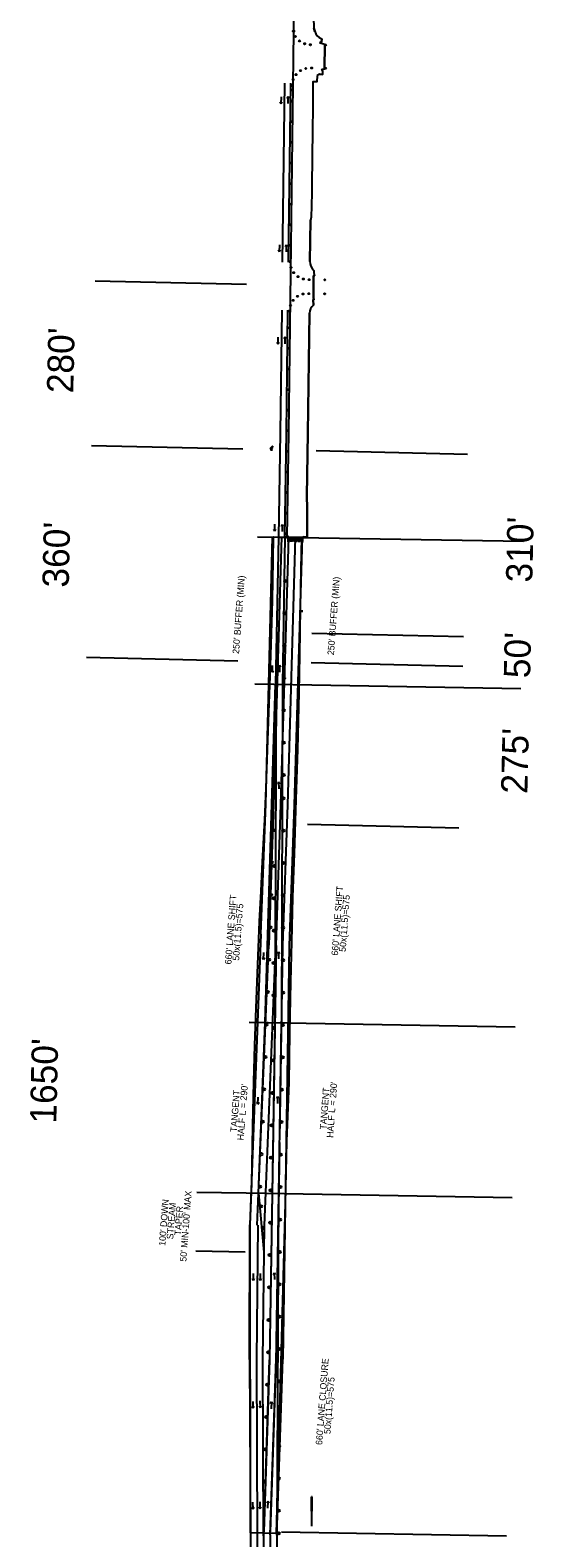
# Model space of a CAD drawing. Extents: x 1650647 to 1653016, y 602856 to 611467.
# Drawn here: x 1652100 to 1652957, y 604352 to 606913 of the extents above; entities that cross this region are included whole.
import ezdxf

# ---------------------------------------------------------------- set-up
doc = ezdxf.new("R2010")
doc.units = 0
for name, color, linetype in [('CM_Corridor_Design', 7, 'Continuous'), ('Default', 7, 'Continuous'), ('DT_X_Break_Line', 7, 'Continuous'), ('DT_X_Contour_Major', 7, 'Continuous'), ('DT_X_Void', 7, 'Continuous'), ('GE_P_Alignment_500_Bearings', 7, 'Continuous'), ('GE_P_Alignment_500_Stations', 7, 'Continuous'), ('MD_P_Intersection_MatchLine', 7, 'Continuous'), ('PF_P_Grade_Line', 7, 'Continuous'), ('PF_X_Ground_Line', 7, 'Continuous'), ('PF_X_Ground_Line_RT', 7, 'Continuous'), ('PV_P_Curb', 7, 'Continuous'), ('PV_P_EOP', 7, 'Continuous'), ('PV_X_EOP', 7, 'Continuous'), ('SC_Scratch1', 7, 'Continuous'), ('UT_X_Water', 7, 'Continuous')]:
    doc.layers.add(name, color=color, linetype=linetype)

msp = doc.modelspace()

# ---------------------------------------------------------------- linework, layer by layer
at = {"layer": 'CM_Corridor_Design'}
for p, q in [((1652527.1, 606787.9), (1652525.5, 606791.3)), ((1652527.1, 606787.9), (1652527.3, 606799.8)), ((1652527.1, 606787.9), (1652528.9, 606791.3)), ((1652538.4, 606800.7), (1652536.6, 606797.4)), ((1652538.4, 606800.7), (1652538.3, 606788.9)), ((1652538.4, 606800.7), (1652540.1, 606797.3)), ((1652524.3, 606536.8), (1652522.6, 606540.2)), ((1652524.3, 606536.8), (1652524.5, 606548.7)), ((1652524.3, 606536.8), (1652526.1, 606540.2)), ((1652535.6, 606548.8), (1652533.8, 606545.4)), ((1652535.6, 606548.8), (1652535.4, 606536.9)), ((1652535.6, 606548.8), (1652537.2, 606545.4)), ((1652521.7, 606380), (1652520, 606383.4)), ((1652521.7, 606380), (1652521.8, 606391.9)), ((1652521.7, 606380), (1652523.5, 606383.4)), ((1652533.4, 606392.3), (1652531.6, 606388.9)), ((1652533.4, 606392.3), (1652533.3, 606380.4)), ((1652533.4, 606392.3), (1652535.1, 606388.9)), ((1652516.3, 606062.2), (1652514.7, 606065.6)), ((1652516.3, 606062.2), (1652516.5, 606074.1)), ((1652516.3, 606062.2), (1652518.1, 606065.6)), ((1652528.7, 606073.6), (1652526.9, 606070.2)), ((1652528.7, 606073.6), (1652528.6, 606061.7)), ((1652528.7, 606073.6), (1652530.4, 606070.2)), ((1652512.3, 605822.3), (1652512.4, 605834.1)), ((1652524.3, 605834.6), (1652522.6, 605831.2)), ((1652524.3, 605834.6), (1652524.2, 605822.7)), ((1652524.3, 605834.6), (1652526, 605831.2)), ((1652512.3, 605822.3), (1652510.6, 605825.7)), ((1652512.3, 605822.3), (1652514.1, 605825.6)), ((1652522.7, 605636.4), (1652521.1, 605633)), ((1652522.7, 605636.4), (1652522.9, 605624.5)), ((1652522.7, 605636.4), (1652524.5, 605633)), ((1652497.1, 605334.3), (1652497.6, 605346.1)), ((1652522.4, 605347.5), (1652520.7, 605344.2)), ((1652522.4, 605347.5), (1652522.6, 605335.7)), ((1652522.4, 605347.5), (1652524.2, 605344.2)), ((1652497.1, 605334.3), (1652495.5, 605337.7)), ((1652497.1, 605334.3), (1652499, 605337.6)), ((1652487.6, 605088.7), (1652486.1, 605092.1)), ((1652487.6, 605088.7), (1652488.1, 605100.5)), ((1652487.6, 605088.7), (1652489.5, 605092)), ((1652520.6, 605101.6), (1652518.9, 605098.2)), ((1652520.6, 605101.6), (1652520.7, 605089.8)), ((1652520.6, 605101.6), (1652522.3, 605098.3)), ((1652479.7, 604788.9), (1652478.1, 604792.3)), ((1652479.7, 604788.9), (1652479.9, 604800.8)), ((1652479.7, 604788.9), (1652481.5, 604792.3)), ((1652491.8, 604789.2), (1652490.2, 604792.6)), ((1652491.8, 604789.2), (1652492, 604801)), ((1652491.8, 604789.2), (1652493.6, 604792.5)), ((1652515.3, 604802.2), (1652513.6, 604798.8)), ((1652515.3, 604802.2), (1652515.4, 604790.4)), ((1652515.3, 604802.2), (1652517, 604798.9)), ((1652479.6, 604571.8), (1652479.4, 604583.6)), ((1652491.7, 604572.5), (1652491.5, 604584.3)), ((1652510.4, 604582.7), (1652508.5, 604579.4)), ((1652510.4, 604582.7), (1652509.9, 604570.8)), ((1652510.4, 604582.7), (1652512, 604579.2)), ((1652479.6, 604571.8), (1652477.8, 604575.1)), ((1652479.6, 604571.8), (1652481.3, 604575.2)), ((1652491.7, 604572.5), (1652489.9, 604575.8)), ((1652491.7, 604572.5), (1652493.4, 604575.9)), ((1652479.3, 604400.6), (1652477.5, 604403.9)), ((1652479.3, 604400.6), (1652479, 604412.4)), ((1652479.3, 604400.6), (1652480.9, 604404)), ((1652491.4, 604401.3), (1652489.6, 604404.6)), ((1652491.4, 604401.3), (1652491.1, 604413.1)), ((1652491.4, 604401.3), (1652493, 604404.7)), ((1652504.2, 604413.8), (1652502.4, 604410.5)), ((1652504.2, 604413.8), (1652503.8, 604402)), ((1652504.2, 604413.8), (1652505.8, 604410.4))]:
    msp.add_line(p, q, dxfattribs=at)
at = {"layer": 'Default'}
msp.add_lwpolyline([(1652561.5, 606051.4), (1652560.7, 605997.6), (1652559.5, 605931.6), (1652558.1, 605851.7), (1652556.8, 605787.9), (1652554.7, 605691), (1652552.1, 605605.9), (1652548.9, 605514.1), (1652546.4, 605440.2), (1652544.3, 605364.6), (1652542.7, 605296.2), (1652541.1, 605209.6), (1652539.8, 605125.1), (1652536.1, 605025.9), (1652533.9, 604920.6), (1652518.7, 604359.2), (1652474.9, 604360), (1652474.2, 604883.4), (1652477.4, 604953.6), (1652478.9, 605051.2), (1652480.7, 605126.3), (1652482.5, 605188.7), (1652484.6, 605251.8), (1652486.1, 605296.5), (1652488.3, 605354.7), (1652490, 605399), (1652492.8, 605450.4), (1652495.3, 605500.8), (1652499, 605571.5), (1652501.4, 605625.4), (1652503.9, 605690.8), (1652506.2, 605754), (1652508.3, 605815.7), (1652510.1, 605869.3), (1652512, 605944.5), (1652513.5, 606013), (1652513.9, 606052.2)], close=True, dxfattribs=at)
at = {"layer": 'DT_X_Break_Line'}
for centre, radius in [((1652547.7, 606911.6), 1), ((1652551.5, 606902.4), 1), ((1652558.2, 606895), 1), ((1652566.9, 606890.2), 1), ((1652576.7, 606888.5), 1), ((1652602.4, 606888.1), 1), ((1652552.3, 606837.8), 1), ((1652559.8, 606844.4), 1), ((1652569, 606848.2), 1), ((1652578.9, 606848.9), 1), ((1652602.5, 606848.4), 1), ((1652545.6, 606811.7), 1), ((1652545.7, 606819.3), 1), ((1652547.4, 606829.1), 1), ((1652545.4, 606792.6), 1), ((1652545, 606757.6), 1), ((1652544.6, 606722.6), 1), ((1652544.1, 606687.6), 1), ((1652543.7, 606652.6), 1), ((1652543.3, 606617.6), 1), ((1652542.9, 606582.6), 1), ((1652542.4, 606547.6), 1), ((1652542, 606519.9), 1), ((1652543.6, 606510.1), 1), ((1652548.2, 606501.3), 1), ((1652555.5, 606494.5), 1), ((1652564.6, 606490.5), 1), ((1652574.5, 606489.5), 1), ((1652601.3, 606489.2), 1), ((1652542.8, 606445.9), 1), ((1652547.5, 606454.3), 1), ((1652554.8, 606461), 1), ((1652564, 606464.9), 1), ((1652573.9, 606465.7), 1), ((1652601, 606465.4), 1), ((1652541, 606436.1), 1), ((1652540.8, 606407.6), 1), ((1652540.3, 606372.6), 1), ((1652539.9, 606337.6), 1), ((1652539.5, 606302.6), 1), ((1652539.1, 606267.6), 1), ((1652538.6, 606232.7), 1), ((1652538.1, 606197.7), 1), ((1652537.5, 606162.7), 1), ((1652536.9, 606127.7), 1), ((1652536.3, 606092.7), 1), ((1652535.5, 606051.8), 1), ((1652535.6, 606057.7), 1), ((1652534, 605977.5), 2), ((1652533, 605922.6), 2), ((1652532.5, 605867.6), 2), ((1652531.6, 605812.7), 2), ((1652531.3, 605757.8), 2), ((1652531.1, 605702.9), 2), ((1652531, 605647.9), 2), ((1652514.6, 605608.7), 2), ((1652530.8, 605608.1), 2), ((1652513.4, 605553.6), 2), ((1652530.7, 605553.2), 2), ((1652510.6, 605499.2), 2), ((1652530.4, 605498.3), 2), ((1652515.1, 605493.4), 2), ((1652509.8, 605443.7), 2), ((1652514.7, 605438.3), 2), ((1652530.2, 605443.2), 2), ((1652508.4, 605388.9), 2), ((1652514.6, 605383.3), 2), ((1652530.2, 605388.2), 2), ((1652506.3, 605333.8), 2), ((1652514.3, 605328.2), 2), ((1652530, 605333.2), 2), ((1652504.2, 605278.9), 2), ((1652514.2, 605273.2), 2), ((1652529.9, 605278.1), 2), ((1652501.9, 605223.8), 2), ((1652514, 605217.7), 2), ((1652529.6, 605223.2), 2), ((1652499.8, 605168.9), 2), ((1652529.3, 605168.2), 2), ((1652513.2, 605162.8), 2), ((1652497.6, 605113.8), 2), ((1652528.1, 605113.1), 2), ((1652512.1, 605107.6), 2), ((1652495.5, 605058.7), 2), ((1652511, 605052.5), 2), ((1652527, 605058), 2), ((1652493.1, 605003.6), 2), ((1652509.9, 604997.4), 2), ((1652526.3, 605002.8), 2), ((1652490.8, 604948.4), 2), ((1652509.3, 604942.2), 2), ((1652525.5, 604947.7), 2), ((1652492.7, 604915.1), 2), ((1652508.3, 604887.3), 2), ((1652524.8, 604892.5), 2), ((1652495.9, 604878.4), 2), ((1652507.6, 604832.1), 2), ((1652524.6, 604837.6), 2), ((1652524.1, 604782.7), 2), ((1652506.8, 604777.2), 2), ((1652505.8, 604722.1), 2), ((1652524, 604727.5), 2), ((1652504.9, 604667.1), 2), ((1652523.7, 604672.6), 2), ((1652503.4, 604612.1), 2), ((1652503.4, 604612.1), 2), ((1652523.5, 604617.7), 2), ((1652523.5, 604617.7), 2), ((1652501.7, 604557.3), 2), ((1652523.3, 604562.8), 2), ((1652499.9, 604502.1), 2), ((1652523.1, 604507.8), 2), ((1652498.3, 604447.2), 2), ((1652522.9, 604452.9), 2), ((1652522.7, 604398), 2), ((1652522.9, 604359.6), 2)]:
    msp.add_circle(centre, radius, dxfattribs=at)
at = {"layer": 'DT_X_Contour_Major'}
for p, q in [((1652548.3, 606910.6), (1652548.3, 606912.4)), ((1652584.1, 606911.2), (1652582.6, 606916.8)), ((1652595.4, 606892.9), (1652592.3, 606891.9)), ((1652595.4, 606892.9), (1652595.9, 606898.5)), ((1652600.4, 606846.9), (1652601.1, 606889.7)), ((1652592.4, 606838.4), (1652597.2, 606838.2)), ((1652600.4, 606846.9), (1652596.3, 606846.4)), ((1652597.2, 606844.4), (1652596.3, 606846.4)), ((1652597.2, 606844.4), (1652597.2, 606838.2)), ((1652580.8, 606807.8), (1652580.6, 606794)), ((1652576, 606520.2), (1652576.9, 606590.3)), ((1652581.7, 606457.6), (1652582.2, 606496)), ((1652582.2, 606496), (1652583.4, 606496.7)), ((1652537, 606051.8), (1652564.5, 606051.3)), ((1652564.5, 606051.3), (1652564.6, 606052.2)), ((1652571.1, 606052.1), (1652564.6, 606052.2))]:
    msp.add_line(p, q, dxfattribs=at)
for points in [[(1652548.3, 606912.4), (1652551.8, 607199.3), (1652552.1, 607225.4)], [(1652584.6, 607225.2), (1652582, 607012), (1652582, 607012), (1652582, 607012), (1652582, 607012), (1652581.7, 606935.1), (1652582.6, 606916.7), (1652582.6, 606916.8), (1652582.6, 606916.6), (1652582.6, 606916.7), (1652584, 606911.4)], [(1652537.5, 606051.8), (1652537, 606051.8), (1652540, 606229.1), (1652548.3, 606910.8)], [(1652595.9, 606898.5), (1652595.4, 606892.9), (1652592.3, 606891.9)], [(1652601.1, 606889.7), (1652600.4, 606846.9), (1652596.3, 606846.4), (1652597.2, 606844.4), (1652597.2, 606838.2), (1652592.4, 606838.4)], [(1652588.2, 606836.1), (1652587.9, 606825.7), (1652580.9, 606825.6), (1652580.8, 606807.8), (1652580.6, 606794), (1652580.2, 606731.2), (1652579.9, 606709.3), (1652578.9, 606637.3), (1652578.6, 606614.6), (1652578, 606595.3), (1652576.9, 606590.2), (1652576.9, 606590.3), (1652576.9, 606590.1), (1652576.9, 606590.2), (1652576, 606520.9)], [(1652588.2, 606836.1), (1652587.9, 606825.7), (1652580.9, 606825.6), (1652580.8, 606807.8)], [(1652580.6, 606794), (1652580.2, 606731.2), (1652579.9, 606709.3), (1652578.9, 606637.3), (1652578.6, 606614.6), (1652578, 606595.3), (1652576.9, 606590.1)], [(1652582.5, 606505.1), (1652582.3, 606501.1), (1652583.4, 606496.7), (1652582.2, 606496), (1652581.7, 606457.6), (1652582.9, 606456), (1652581.4, 606454.9), (1652581.7, 606445.8)], [(1652582.5, 606505.1), (1652582.3, 606501.1), (1652583.4, 606496.7)], [(1652581.7, 606445.8), (1652581.4, 606454.9), (1652582.9, 606456), (1652581.7, 606457.6)], [(1652575, 606432.5), (1652572.5, 606228.6), (1652570.7, 606121.8), (1652570.7, 606121.8), (1652570.7, 606121.8), (1652570.7, 606121.8), (1652571.1, 606101.9), (1652571.3, 606077.5), (1652571.1, 606052.1), (1652564.6, 606052.2), (1652564.5, 606051.3), (1652539.5, 606051.7)], [(1652570.7, 606121.8), (1652572.5, 606228.6), (1652575, 606432.5)], [(1652571.1, 606052.1), (1652571.3, 606077.5), (1652571.1, 606101.9), (1652570.7, 606121.8)]]:
    msp.add_lwpolyline(points, dxfattribs=at)
for centre, radius, start, end in [((1652548.8, 606911.6), 1, 236.0828, 122.529), ((1652602.4, 606916.4), 19, 195.042, 250.167), ((1652602.4, 606916.4), 19, 195.042, 250.167), ((1652603.1, 606916.6), 27, 246.3312, 265.7395), ((1652603.1, 606916.6), 27, 246.3312, 265.7395), ((1652600.2, 606819.5), 20.5, 112.4368, 125.8239), ((1652600.2, 606819.5), 20.5, 112.4368, 125.8239), ((1652598, 606520.6), 22, 179.3069, 225.0406), ((1652598, 606520.6), 22, 179.3069, 225.0406), ((1652592, 606432.3), 17, 127.2779, 179.3069), ((1652592, 606432.3), 17, 127.2779, 179.3069), ((1652538.5, 606051.8), 1, 359.0173, 179.0173)]:
    msp.add_arc(centre, radius, start, end, dxfattribs=at)
at = {"layer": 'DT_X_Void'}
for p, q in [((1652539.5, 606048.4), (1652549.5, 606048.3)), ((1652539.5, 606046.4), (1652549.5, 606046.3)), ((1652546.5, 606044.9), (1652542.5, 606044.9)), ((1652543.5, 606046.4), (1652543.5, 606044.9)), ((1652544.5, 606047.4), (1652544.5, 606047.4)), ((1652545.5, 606046.4), (1652545.5, 606044.9)), ((1652552.4, 606048.4), (1652562.4, 606048.3)), ((1652552.4, 606046.4), (1652562.4, 606046.3)), ((1652559.4, 606044.8), (1652555.4, 606044.8)), ((1652556.4, 606046.3), (1652556.4, 606044.8)), ((1652557.4, 606047.3), (1652557.4, 606047.3)), ((1652558.4, 606046.3), (1652558.4, 606044.8))]:
    msp.add_line(p, q, dxfattribs=at)
for points in [[(1652538.6, 606050.5), (1652538.5, 606044.5), (1652539.5, 606044.4), (1652539.6, 606050.4)], [(1652550.6, 606050.3), (1652550.5, 606044.3), (1652549.5, 606044.3), (1652549.6, 606050.3)], [(1652551.4, 606050.4), (1652551.4, 606044.4), (1652552.4, 606044.4), (1652552.4, 606050.4)], [(1652563.4, 606050.3), (1652563.4, 606044.3), (1652562.4, 606044.3), (1652562.4, 606050.3)]]:
    msp.add_lwpolyline(points, close=True, dxfattribs=at)
at = {"layer": 'GE_P_Alignment_500_Bearings'}
for p, q in [((1652500, 605227.3), (1652517.6, 605802.1)), ((1652518.6, 605802.1), (1652516.3, 605226.9)), ((1652488.2, 604937.5), (1652500, 605227.3)), ((1652516.3, 605227), (1652511.5, 604937.1)), ((1652488.2, 604937.5), (1652497.4, 604837.3))]:
    msp.add_line(p, q, dxfattribs=at)
msp.add_lwpolyline([(1652511.5, 604937.1), (1652507, 604654.3), (1652497.6, 604362.2)], dxfattribs=at)
at = {"layer": 'GE_P_Alignment_500_Stations'}
msp.add_lwpolyline([(1652508.6, 604362), (1652518.3, 604648.3), (1652522.8, 604936.9)], dxfattribs=at)
at = {"layer": 'MD_P_Intersection_MatchLine'}
for p, q in [((1652510.8, 606204.9), (1652512, 606204.9)), ((1652511.2, 606206.1), (1652512, 606206.1))]:
    msp.add_line(p, q, dxfattribs=at)
msp.add_lwpolyline([(1652511.2, 606206.1), (1652509.6, 606200.1), (1652512, 606200.1)], dxfattribs=at)
msp.add_circle((1652510.3, 606202.9), 1.3, dxfattribs=at)
msp.add_arc((1652512, 606205.5), 0.638, 268.8767, 91.1233, dxfattribs=at)
at = {"layer": 'PF_P_Grade_Line'}
for p, q in [((1652527.5, 606052.2), (1652514, 605598)), ((1652551, 606051.5), (1652537.5, 605597.3)), ((1652514, 605598.1), (1652505.8, 605358.8)), ((1652537.5, 605597.3), (1652529.3, 605358.1)), ((1652505.3, 605358.9), (1652485.9, 604882.9)), ((1652529.3, 605358.1), (1652524.2, 605028.7)), ((1652524.2, 605023.7), (1652518.5, 604655.6)), ((1652487.4, 604882.7), (1652484.9, 604654.5)), ((1652484.9, 604654.5), (1652486.4, 604355.4)), ((1652508.4, 604356.6), (1652518.5, 604655.6)), ((1652486.4, 604355.4), (1652478.6, 603642.8)), ((1652508.4, 604356.6), (1652500.6, 603644))]:
    msp.add_line(p, q, dxfattribs=at)
at = {"layer": 'PF_X_Ground_Line'}
for p, q in [((1652560.9, 605926.4), (1652564.1, 605926.3)), ((1652562.5, 605926.4), (1652562.6, 605928)), ((1652562.5, 605926.4), (1652562.5, 605926.4))]:
    msp.add_line(p, q, dxfattribs=at)
at = {"layer": 'PF_X_Ground_Line_RT'}
for p, q in [((1652486.7, 606052.6), (1652938.9, 606044.9)), ((1652482.5, 605802.7), (1652934.6, 605794.9)), ((1652472.6, 605227.8), (1652924.7, 605220)), ((1652383.8, 604939.2), (1652467.6, 604937.8)), ((1652467.6, 604937.8), (1652919.7, 604930.1)), ((1652382.1, 604839.3), (1652465.9, 604837.8)), ((1652579.8, 604421.7), (1652578.8, 604421.7)), ((1652579.1, 604371.7), (1652578.8, 604421.7)), ((1652579.1, 604371.7), (1652579.8, 604421.7)), ((1652527.5, 604361.7), (1652909.9, 604355.1))]:
    msp.add_line(p, q, dxfattribs=at)
at = {"layer": 'PV_P_Curb'}
for p, q in [((1652539.5, 606051.9), (1652526, 605597.7)), ((1652526, 605597.7), (1652517.8, 605358.4)), ((1652517.3, 605358.4), (1652497.9, 604882.4)), ((1652518.3, 605358.4), (1652507, 604654.3)), ((1652497.9, 604882.4), (1652495.4, 604654.4)), ((1652495.4, 604654.4), (1652496.4, 604355.3)), ((1652497.4, 604355.3), (1652507, 604654.3)), ((1652496.9, 604355.3), (1652489.1, 603642.7))]:
    msp.add_line(p, q, dxfattribs=at)
at = {"layer": 'PV_P_EOP'}
for p, q in [((1652539.5, 606519.1), (1652543.2, 606823)), ((1652543.5, 606515.7), (1652544.1, 606565.7)), ((1652536, 606229.1), (1652538.5, 606437.7)), ((1652533, 606051.9), (1652536, 606229.1)), ((1652533, 606051.9), (1652529.2, 605801.9)), ((1652529.2, 605801.9), (1652527.3, 605226.8)), ((1652522.8, 604936.9), (1652527.3, 605226.8)), ((1652520.1, 604361.8), (1652522.8, 604936.9))]:
    msp.add_line(p, q, dxfattribs=at)
at = {"layer": 'PV_X_EOP'}
for p, q in [((1652529.5, 606519.2), (1652533.2, 606823.1)), ((1652526, 606229.2), (1652528.5, 606437.8)), ((1652523, 606052), (1652526, 606229.3)), ((1652518.1, 605802.1), (1652523, 606052))]:
    msp.add_line(p, q, dxfattribs=at)
at = {"layer": 'SC_Scratch1'}
for p, q in [((1652562.5, 606051.2), (1652549, 605597)), ((1652549, 605597), (1652540.8, 605357.7)), ((1652492.7, 605377.5), (1652474, 604883.4)), ((1652540.8, 605357.7), (1652530, 604655.4)), ((1652473.4, 604654.8), (1652474, 604883.4)), ((1652473.4, 604654.8), (1652474.9, 604355.7)), ((1652519.9, 604356.4), (1652530, 604655.4)), ((1652474.9, 604355.7), (1652467.1, 603643.1)), ((1652519.9, 604356.4), (1652512.1, 603643.8))]:
    msp.add_line(p, q, dxfattribs=at)
msp.add_lwpolyline([(1652492.7, 605377.4), (1652500.7, 605598.5), (1652512.5, 606052.2)], dxfattribs=at)
at = {"layer": 'UT_X_Water'}
for p, q in [((1652468.2, 606481.1), (1652210.8, 606487.1)), ((1652461.8, 606201.2), (1652204.3, 606207.2)), ((1652844, 606192.3), (1652586.6, 606198.3)), ((1652836.8, 605882.4), (1652579.4, 605888.4)), ((1652453.4, 605841.3), (1652195.9, 605847.3)), ((1652835.7, 605832.4), (1652578.2, 605838.4)), ((1652829.3, 605557.5), (1652571.8, 605563.5))]:
    msp.add_line(p, q, dxfattribs=at)

# ---------------------------------------------------------------- texts
at = {"layer": 'PF_X_Ground_Line_RT'}
for s, p in [("250' BUFFER (MIN)", (1652455.3, 605853.2)), ("250' BUFFER (MIN)", (1652616.7, 605851.1)), ("660' LANE SHIFT", (1652623.5, 605340.6)), ("660' LANE SHIFT", (1652442.3, 605325.7)), ('50x(11.5)=575', (1652455.4, 605332.1)), ('50x(11.5)=575', (1652636.6, 605347)), ("HALF L = 290'", (1652463.2, 605026.8)), ('TANGENT', (1652603.8, 605045)), ("HALF L = 290'", (1652615.3, 605031)), ('TANGENT', (1652451.6, 605040.8)), ("50' MIN-100' MAX", (1652365.8, 604820.6)), ("100' DOWN", (1652330, 604847.5)), ('STREAM', (1652343.4, 604858.6)), ('TAPER', (1652356.6, 604865.3)), ("660' LANE CLOSURE", (1652596.7, 604509.2)), ('50x(11.5)=575', (1652610.7, 604527.7))]:
    msp.add_text(s, height=11.2, rotation=85.6823, dxfattribs=at).set_placement(p)
at = {"layer": 'UT_X_Water'}
for s, p in [("280'", (1652173.4, 606296.1)), ("360'", (1652165.7, 605965.9)), ("310'", (1652953.9, 605974.5)), ("50'", (1652950.2, 605811.9)), ("275'", (1652945.6, 605615.5)), ("1650'", (1652144.6, 605055.2))]:
    msp.add_text(s, height=44.8, rotation=88.672, dxfattribs=at).set_placement(p)

doc.saveas('drawing.dxf')
